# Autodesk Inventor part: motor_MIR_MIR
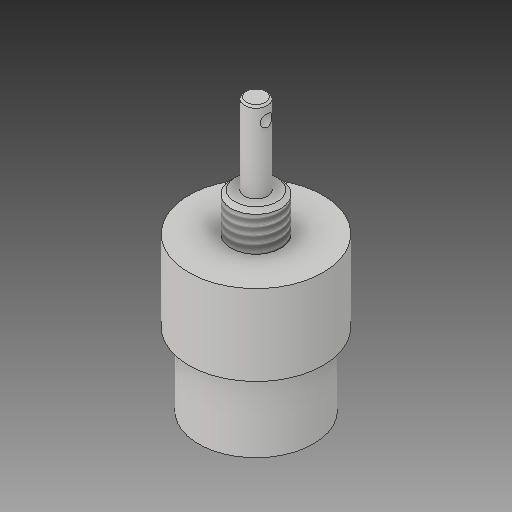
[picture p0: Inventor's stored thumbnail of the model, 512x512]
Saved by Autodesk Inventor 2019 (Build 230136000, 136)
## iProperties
Created: 2019-10
Part Number: motor_MIR_MIR
Material: Generic
Document SubType Name: Modeling
Designer: PRADYUMNA
Density: 1 g/cm^3
Appearance: Default
Author: Asus
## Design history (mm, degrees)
derived "motor_MIR.ipt"
  sketch "Sketch1"
    geometry: C1 r 6.5 at (0, 0) reference; 1 further point
  sketch "Sketch2"
    geometry: 1 further point
  sketch "Sketch3"
    geometry: C1 r 17.5 at (0, 0) reference; 1 further point
  sketch "Sketch4"
    geometry: C1 r 15 at (0, 0) reference; 1 further point
  sketch "Sketch5"
    geometry: C1 r 3 at (0, 0) reference; 1 further point
  sketch "Sketch6"
    geometry: C1 r 1.55 at (27.143, 0) reference; 1 further point
  sketch "Sketch7"
    geometry: L1 (12.192, 2.12)-(11.485, 2.12) reference; L2 (11.485, 2.12)-(11.485, -2.356) reference; L3 (11.485, -2.356)-(12.192, -2.356) reference; L4 (12.192, -2.356)-(12.192, 2.12) reference; L5 (-11.603, 2.12)-(-12.546, 2.12) reference; L6 (-12.546, 2.12)-(-12.546, -2.356) reference; L7 (-12.546, -2.356)-(-11.603, -2.356) reference; L8 (-11.603, -2.356)-(-11.603, 2.12) reference; 1 further point
feature "Solid1::motor_MIR.ipt"
tag "TaggingFeature1"
body "Solid1"
